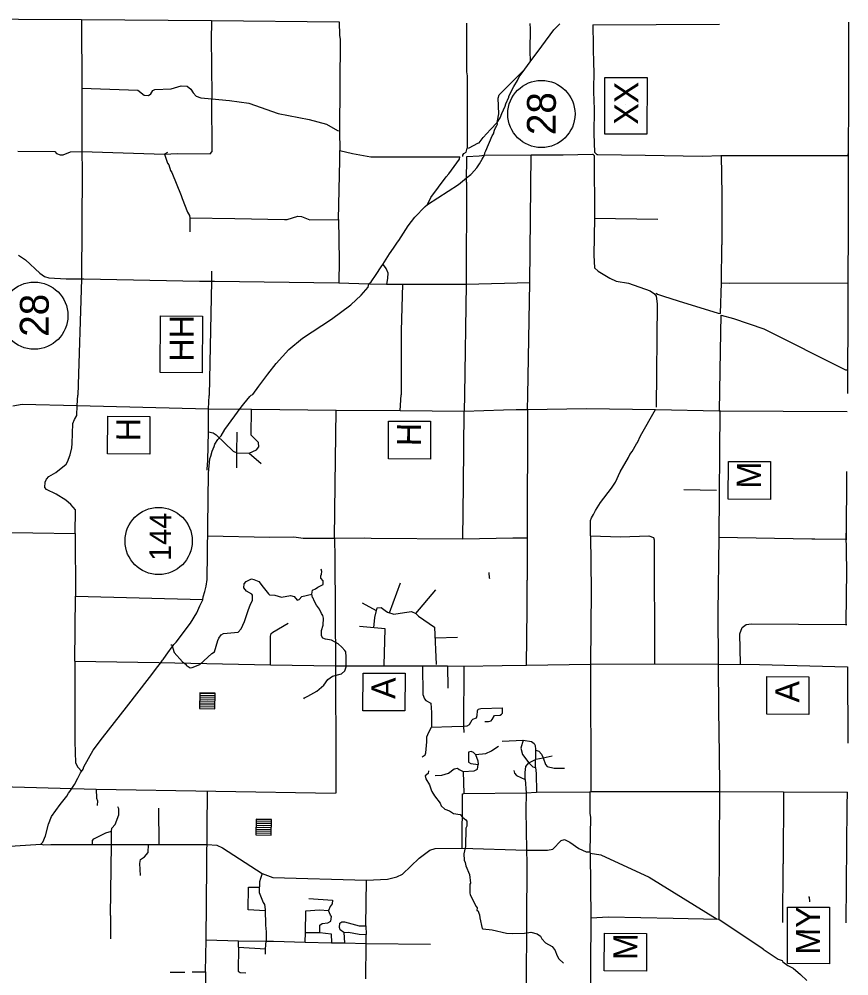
# Model space of a CAD drawing. Extents: x 299354 to 1325680, y 96128 to 228242.
# Drawn here: x 365592 to 400121, y 187967 to 227772 of the extents above; entities that cross this region are included whole.
import ezdxf

# ---------------------------------------------------------------- set-up
doc = ezdxf.new("R2010")
doc.units = 0
for name, color, linetype in [('Level 12', 7, 'Continuous'), ('Level 13', 7, 'Continuous'), ('Level 2', 7, 'Continuous'), ('Level 4', 7, 'Continuous'), ('Level 51', 7, 'Continuous'), ('Level 57', 7, 'Continuous')]:
    doc.layers.add(name, color=color, linetype=linetype)

msp = doc.modelspace()

# ---------------------------------------------------------------- linework, layer by layer
at = {"layer": 'Level 12'}
for p, q in [((387326, 223827), (387326, 223827)), ((366223, 215436), (366223, 215436)), ((371396, 206061), (371396, 206061))]:
    msp.add_line(p, q, dxfattribs=at)
for centre in [(387326, 223827), (366223, 215436), (371396, 206061)]:
    msp.add_circle(centre, 1398, dxfattribs=at)
at = {"layer": 'Level 13'}
for p, q in [((390818, 224213), (390818, 224213)), ((372319, 214294), (372319, 214294)), ((370132, 210496), (370132, 210496)), ((381816, 210290), (381816, 210290)), ((395959, 208614), (395959, 208614)), ((380754, 199812), (380754, 199812)), ((397557, 199665), (397557, 199665)), ((398418, 189701), (398418, 189701)), ((390800, 188986), (390800, 188986))]:
    msp.add_line(p, q, dxfattribs=at)
for points in [[(391711, 222982), (389961, 222989), (389970, 225344), (391720, 225337)], [(373211, 213063), (371461, 213070), (371471, 215425), (373221, 215418)], [(371026, 209675), (369276, 209682), (369282, 211252), (371032, 211245)], [(382710, 209469), (380960, 209476), (380966, 211046), (382716, 211039)], [(396853, 207792), (395103, 207800), (395109, 209370), (396859, 209362)], [(381648, 198990), (379898, 198997), (379904, 200567), (381654, 200560)], [(398451, 198844), (396701, 198851), (396708, 200421), (398458, 200414)], [(399311, 188470), (397561, 188477), (397570, 190832), (399320, 190825)], [(391694, 188164), (389944, 188171), (389950, 189741), (391700, 189734)]]:
    msp.add_lwpolyline(points, close=True, dxfattribs=at)
at = {"layer": 'Level 2'}
for points in [[(384951, 222118), (384968, 222210), (385019, 222293), (385275, 222916), (385326, 222999), (385377, 223148), (385412, 223248), (385437, 223289), (385505, 223406), (385489, 223472), (385607, 223671), (385676, 223846), (385812, 224145), (385846, 224253), (385974, 224519), (385974, 224569), (386178, 224975), (386330, 225224), (386398, 225365), (386635, 225688), (386854, 225995), (387344, 226641), (387842, 227320), (388053, 227535), (388086, 227574)], [(389471, 227539), (389488, 225813), (389504, 225688)], [(385489, 223472), (385559, 223830), (385531, 224489), (385566, 224622), (386113, 225159), (386635, 225688)], [(389504, 225688), (389496, 224746), (389522, 224029), (389513, 222995), (389540, 222236), (389630, 222135), (389676, 222134)], [(385202, 223175), (385489, 223472)], [(384730, 222620), (384908, 222852), (385202, 223175)], [(384236, 222408), (384320, 222415), (384680, 222612), (384730, 222620)], [(380140, 216766), (380241, 216840), (380444, 217147), (380655, 217470), (380723, 217570), (381010, 218009), (381171, 218241), (381340, 218498), (381391, 218564), (381788, 219170), (382058, 219534), (382488, 219972), (382589, 220063), (383872, 220894), (384208, 221166), (384385, 221306), (384418, 221331), (384637, 221579), (384756, 221753), (384866, 221952), (384951, 222118)], [(384050, 222059), (384050, 222118), (384101, 222184), (384201, 222233)], [(384201, 222233), (384236, 222408)], [(384951, 222118), (386894, 222126), (387120, 222124), (387286, 222122), (388237, 222131), (389455, 222153), (389464, 222147)], [(389464, 222147), (389522, 222103), (389532, 219493), (389509, 217951), (389538, 217425), (389687, 217282), (390176, 216994), (390442, 216875), (390951, 216792), (391850, 216461), (392033, 216342), (392107, 216249), (392138, 215930), (392103, 211623)], [(382589, 220063), (382725, 220345), (383366, 221207), (383468, 221339), (383915, 221944), (383933, 222044)], [(365562, 217954), (365852, 217752), (366456, 217204), (366647, 217069), (366830, 217009), (367555, 216969), (368206, 216964), (368289, 216963), (373101, 216870), (373601, 216866), (373726, 216865), (378897, 216794), (380140, 216766)], [(373596, 216867), (373596, 216864), (373496, 212108)], [(375247, 212122), (375314, 212155), (375561, 212498), (375944, 213006), (376284, 213448), (376817, 214023), (377384, 214498), (378584, 215296), (379398, 215881), (379827, 216286), (380114, 216625), (380140, 216766)], [(365003, 193346), (366497, 193449), (366581, 193532), (366692, 193789), (366813, 194272), (366933, 194595), (367296, 195101), (367582, 195440), (367650, 195572), (367701, 195639), (367896, 195928), (368031, 196194), (368150, 196418), (368252, 196567), (368278, 196667), (368668, 197355), (369064, 197876), (370060, 199142), (371022, 200384), (371360, 200839), (371470, 200971), (371554, 201095), (371588, 201129), (371707, 201311), (372036, 201749), (372120, 201849), (372720, 202643), (372990, 203074), (373118, 203365), (373237, 203614), (373255, 203738), (373324, 203955), (373342, 204071), (373376, 204179), (373412, 204462), (373469, 208887), (373525, 209478), (373576, 209594), (373620, 209794), (373705, 209985), (373739, 210084), (373858, 210283), (373994, 210442), (374156, 210693), (374830, 211629), (374949, 211763), (375188, 212072), (375247, 212122)], [(373477, 211562), (373496, 212108)], [(365331, 211685), (365715, 211749), (368008, 211695)], [(368008, 211695), (373477, 211562)], [(373469, 210595), (373477, 211562)], [(373477, 211562), (375262, 211546)], [(375262, 211546), (378781, 211497)], [(378781, 211497), (381450, 211490)], [(381450, 211490), (384110, 211465)], [(384110, 211465), (385753, 211517), (386279, 211529), (386754, 211525)], [(386754, 211525), (389207, 211569), (392075, 211527)], [(392075, 211527), (394718, 211470), (400055, 211452)], [(394746, 211496), (394703, 206219)], [(373421, 209004), (373421, 209054), (373441, 209412), (373469, 210595)], [(394703, 206219), (394674, 203086), (394688, 200936)], [(371409, 200998), (376056, 200913)], [(376056, 200913), (378758, 200872)], [(378758, 200872), (382378, 200873)], [(382378, 200873), (383412, 200863)], [(383412, 200863), (384095, 200857)], [(384095, 200857), (385689, 200876)], [(385689, 200876), (386706, 200892)], [(386706, 200892), (389367, 200934)], [(389367, 200934), (392028, 200943)], [(392028, 200943), (394688, 200936)], [(394688, 200936), (394686, 200694), (394709, 197852), (394722, 197427), (394739, 195635)], [(394688, 200936), (396397, 200921)], [(396397, 200921), (400058, 200821)], [(394739, 195635), (394710, 190918)], [(394710, 190918), (394707, 190327)], [(389386, 190375), (389347, 184284)], [(389386, 190375), (390112, 190419), (392814, 190361), (394701, 190327)], [(394707, 190327), (396553, 189087)], [(396559, 189083), (397185, 188663), (397351, 188612)], [(397351, 188612), (397367, 188545), (397574, 188393), (397807, 188291)], [(397807, 188291), (398113, 188030)], [(398113, 188030), (398378, 187777)]]:
    msp.add_lwpolyline(points, dxfattribs=at)
at = {"layer": 'Level 4'}
for points in [[(368194, 227744), (362929, 227772)], [(368194, 227744), (368202, 224893)], [(373600, 227703), (368194, 227744)], [(373591, 227716), (373583, 226863)], [(378904, 227649), (373600, 227703)], [(378903, 227658), (378904, 227649), (378924, 227107), (378955, 226924), (378921, 223122)], [(384204, 227602), (384215, 225585), (384230, 225409), (384236, 222408)], [(386848, 227589), (386858, 227362), (386850, 226462), (386854, 225995)], [(389471, 227539), (394742, 227566)], [(400110, 227645), (400110, 226211), (400090, 220333)], [(373583, 226863), (373591, 225920)], [(400110, 226211), (400121, 226211)], [(373591, 225920), (373611, 224453)], [(368202, 224893), (370529, 224822), (370794, 224603), (370969, 224601), (371069, 224667), (371154, 224800), (371238, 224841), (371922, 224868), (372340, 224998), (372582, 224979), (372731, 224861), (372830, 224702), (372954, 224567), (373153, 224499), (373611, 224453)], [(368202, 224893), (368200, 223684)], [(371773, 222226), (371639, 222153), (372165, 222181), (373541, 222169), (373625, 222260), (373611, 224453)], [(373611, 224453), (374353, 224388), (375153, 224272), (376367, 223845), (377657, 223592), (378381, 223402), (378838, 223139), (378921, 223122)], [(368200, 223684), (368203, 222258)], [(378921, 223122), (378939, 222313)], [(365543, 222273), (367077, 222260), (367152, 222176), (367301, 222124), (367418, 222123), (367728, 222254), (368203, 222258)], [(368203, 222258), (368211, 221456), (368194, 216951), (368033, 212127)], [(368203, 222258), (371639, 222153), (371769, 221785), (371818, 221709), (371891, 221475), (371941, 221391), (372332, 220437), (372373, 220303), (372601, 219743), (372684, 219600), (372699, 219508)], [(378931, 221900), (378939, 222313)], [(378939, 222313), (379471, 222175), (380221, 222043), (383849, 222044), (383933, 222044)], [(384742, 222078), (384951, 222118)], [(386847, 216815), (386894, 222126)], [(389676, 222134), (391646, 222106)], [(394802, 222098), (400080, 222104), (400107, 222192)], [(394806, 222109), (394837, 220455), (394835, 218387)], [(378888, 219429), (378931, 221900)], [(384207, 220991), (384225, 222058)], [(384225, 222058), (384742, 222078)], [(391646, 222106), (394017, 222071), (394802, 222098)], [(384207, 220991), (384193, 216747)], [(400090, 220330), (400088, 219881)], [(400088, 219863), (400061, 212193)], [(372699, 219508), (372693, 218921)], [(372699, 219508), (374568, 219484), (376636, 219432), (376744, 219431)], [(376744, 219431), (377196, 219577), (377346, 219559), (377687, 219423), (378888, 219429)], [(378888, 219429), (378906, 217736), (378897, 216794)], [(389532, 219493), (392167, 219453)], [(394820, 216795), (394835, 218387)], [(380723, 217570), (380871, 217377), (380936, 217210), (380918, 216976), (380882, 216751)], [(373591, 217291), (373596, 216901)], [(380140, 216766), (380882, 216751)], [(380882, 216751), (381541, 216746)], [(381541, 216746), (381494, 214800), (381486, 212142)], [(381541, 216746), (384193, 216747)], [(384193, 216747), (384130, 212135)], [(384193, 216747), (386847, 216815)], [(386759, 212118), (386847, 216815)], [(394776, 215528), (394820, 216795)], [(394820, 216795), (395137, 216792), (400092, 216807), (400096, 216807)], [(392106, 216369), (392155, 216335), (392405, 216241), (393012, 216052), (394684, 215545), (394776, 215528)], [(394783, 213978), (394808, 215461)], [(394808, 215461), (395316, 215323), (396580, 214887), (399976, 213181), (400043, 213180)], [(394740, 211460), (394783, 213978)], [(368008, 211695), (368033, 212127)], [(381450, 211490), (381486, 212142)], [(384130, 212135), (384110, 211465)], [(386754, 211525), (386759, 212118)], [(367925, 206378), (367934, 207362), (367745, 207580), (367529, 207765), (367140, 208011), (366733, 208198), (366667, 208282), (366669, 208507), (366737, 208639), (366830, 208738), (367115, 208911), (367543, 209257), (367611, 209356), (367714, 209647), (367783, 209938), (367801, 210121), (367826, 210955), (367902, 211120), (367987, 211286), (368008, 211695)], [(375170, 209713), (375463, 209852), (375565, 209984), (375549, 210151), (375252, 210462), (375262, 211546)], [(378743, 208415), (378781, 211497)], [(384082, 208398), (384110, 211465)], [(386754, 211525), (386738, 206192)], [(389366, 206268), (389372, 206909), (389407, 207026), (389491, 207167), (389576, 207333), (389788, 207656), (390244, 208260), (390404, 208508), (390608, 208932), (390956, 209537), (391007, 209653), (391108, 209777), (391278, 210109), (391329, 210158), (391456, 210432), (392075, 211527)], [(373469, 210595), (373660, 210560), (373793, 210475), (374495, 209802), (374653, 209734)], [(374653, 209734), (374661, 210584)], [(374647, 209109), (374653, 209734)], [(374653, 209734), (375170, 209713)], [(375170, 209713), (375658, 209284)], [(400016, 208946), (400007, 206138)], [(400016, 208946), (400022, 208950)], [(378715, 206172), (378743, 208415)], [(384061, 206149), (384082, 208398)], [(394618, 208162), (393253, 208191)], [(362618, 205135), (363636, 205142), (363844, 205190), (363896, 205315), (363918, 205890), (364019, 206072), (364281, 206395), (364381, 206427), (367925, 206378)], [(367925, 206378), (367935, 203770)], [(373429, 206279), (376022, 206222)], [(376022, 206222), (377023, 206229), (377414, 206184)], [(384061, 206149), (386130, 206197), (386738, 206192)], [(386738, 206192), (386739, 204425)], [(389366, 206268), (390617, 206240), (391802, 206279), (391993, 206211), (392025, 206110), (392028, 200943)], [(389366, 206268), (389395, 204017), (389367, 200934)], [(394703, 206219), (398581, 206151), (398706, 206150), (400007, 206138)], [(400015, 202553), (400011, 202673), (400031, 204823), (400012, 206381)], [(377414, 206184), (378715, 206172)], [(378715, 206172), (379958, 206186), (380242, 206184), (384061, 206149)], [(378715, 206172), (378724, 205347)], [(400007, 206138), (400036, 206138)], [(378724, 205347), (378758, 200872)], [(381004, 203069), (381457, 204314)], [(386728, 203208), (386739, 204425)], [(382099, 203049), (382930, 204026)], [(367910, 201062), (367935, 203770)], [(367935, 203770), (373237, 203622)], [(380460, 203160), (379875, 203468)], [(380346, 202452), (380388, 202877), (380495, 203280), (380659, 203298), (380821, 203175), (380918, 203096), (381179, 203013), (381453, 203051), (381728, 203100), (381925, 203128), (382099, 203049), (382206, 202937), (382884, 202474)], [(386706, 200892), (386728, 203208)], [(376056, 200913), (376051, 202105), (376085, 202205), (376152, 202271), (376789, 202640)], [(395606, 200944), (395587, 202199), (395680, 202460), (395841, 202591), (396074, 202607), (399983, 202579)], [(380783, 200888), (380827, 202408), (379756, 202497)], [(382884, 202474), (382949, 200919)], [(382899, 202025), (383828, 202059)], [(367910, 201062), (367912, 197720), (367937, 196836), (368036, 196652), (368201, 196467)], [(367910, 201062), (371409, 200998)], [(378758, 200872), (378770, 196755)], [(382378, 200873), (382392, 199672), (382457, 199488), (382523, 199421), (382722, 199311), (382752, 198927), (382746, 198319)], [(383412, 200863), (383428, 199938)], [(384095, 200857), (384089, 198357)], [(389367, 200934), (389385, 195642)], [(400058, 200821), (400078, 197646)], [(384089, 198357), (384239, 198372), (384340, 198421), (384442, 198620), (384467, 198654), (384618, 198702), (384652, 198802), (384670, 198993), (384688, 199060), (384805, 199092), (385706, 199117)], [(384975, 198549), (385125, 198548), (385242, 198580), (385276, 198630), (385377, 198795), (385603, 198818), (385670, 198851), (385704, 198901), (385706, 199117)], [(382359, 197081), (382485, 197163), (382519, 197246), (382557, 197704), (382559, 197912), (382644, 198112), (382746, 198319)], [(382746, 198319), (383597, 198345), (384089, 198357)], [(384089, 198357), (384103, 198098)], [(384587, 197177), (385013, 197224), (385247, 197330), (385432, 197461), (385541, 197527)], [(385693, 197726), (386561, 197768)], [(386561, 197768), (386466, 197435), (386538, 197176), (386802, 196824)], [(386561, 197768), (386910, 197715), (387026, 197630), (387067, 197547), (387082, 197380), (387099, 197363)], [(384587, 197177), (384504, 197261), (384396, 197304), (384296, 197272), (384292, 196863), (384392, 196796), (384700, 196760)], [(384587, 197177), (384685, 196910), (384700, 196760)], [(387095, 196988), (387099, 197363)], [(387095, 196988), (387396, 197035)], [(387099, 197363), (387215, 197312), (387331, 197186), (387396, 197035)], [(387396, 197035), (387772, 197115)], [(387396, 197035), (387494, 196768), (387568, 196675), (387851, 196606), (388293, 196602)], [(378770, 196755), (378776, 195572)], [(384072, 196474), (384531, 196503), (384665, 196568), (384700, 196760)], [(386646, 196142), (386648, 196434), (386684, 196683), (386802, 196824)], [(386802, 196824), (387079, 196972)], [(386802, 196824), (386967, 196664), (387075, 196630)], [(387075, 196630), (387079, 196972)], [(387079, 196972), (387095, 196988)], [(382902, 196301), (383186, 196315), (383462, 196396), (383697, 196577), (383831, 196609), (383897, 196559), (384072, 196474)], [(384072, 196474), (384097, 195557)], [(386174, 196505), (386206, 196404), (386289, 196304), (386646, 196142)], [(387075, 196630), (387107, 196380), (387116, 195613)], [(362587, 195468), (362737, 195483), (363265, 195762), (363466, 195827), (364300, 195853), (368794, 195729)], [(386646, 196142), (386691, 195583)], [(368794, 195729), (368808, 195362), (368857, 195253), (368838, 195053)], [(368794, 195729), (378764, 195570)], [(373374, 189470), (373431, 195655)], [(384025, 193274), (384046, 195541)], [(384046, 195541), (384097, 195557)], [(384097, 195557), (386691, 195583)], [(386691, 195583), (386684, 194858), (386702, 193200)], [(386691, 195583), (387116, 195613)], [(387116, 195613), (389335, 195626)], [(389335, 195626), (389385, 195642)], [(389335, 195626), (389343, 194734), (389375, 194559), (389345, 193126)], [(389385, 195642), (394739, 195635)], [(394739, 195635), (397399, 195628)], [(397399, 195628), (397383, 192626)], [(397399, 195628), (400060, 195604)], [(400009, 190172), (400054, 195004), (400054, 195046), (400060, 195604)], [(369437, 193981), (369455, 194114), (369590, 194271), (369744, 194670), (369746, 194912), (369697, 194995)], [(371398, 194947), (371400, 193438)], [(368648, 193430), (368650, 193597), (368700, 193663), (369195, 193917), (369437, 193981)], [(369432, 193439), (369437, 193981)], [(386702, 193200), (387586, 193192), (387803, 193240), (388148, 193595), (388282, 193644), (388515, 193533), (388888, 193263), (389195, 193127), (389345, 193126)], [(366513, 193449), (366613, 193415)], [(366613, 193415), (366905, 193429)], [(366905, 193429), (368648, 193430)], [(368648, 193430), (369432, 193439)], [(369388, 190473), (369432, 193439)], [(369432, 193439), (370975, 193426)], [(370638, 192137), (370609, 192645), (370644, 192803), (370812, 192919), (370955, 193101), (370975, 193426)], [(370975, 193426), (371400, 193438)], [(371400, 193438), (373410, 193437)], [(373410, 193437), (373819, 193400), (374059, 193298), (375709, 192233)], [(380043, 191952), (380928, 191994), (381304, 192082), (381539, 192197), (382237, 192865), (382682, 193203), (382908, 193267), (384025, 193274)], [(384025, 193274), (386702, 193200)], [(386702, 193200), (386714, 192675), (386678, 185150)], [(389345, 193126), (389361, 193076)], [(389361, 193076), (389386, 190375)], [(389361, 193076), (389802, 192997), (391811, 192079)], [(397366, 190194), (397383, 192626)], [(375709, 192233), (375641, 192025), (375589, 191875), (375585, 191434), (375748, 191024), (375797, 190940), (375829, 190723), (375840, 190081), (375870, 189806), (375867, 189414)], [(375709, 192233), (376150, 192054), (380043, 191952)], [(380026, 190043), (380043, 191952)], [(391811, 192079), (394640, 190328)], [(375830, 190678), (375119, 190712), (375133, 191655), (375587, 191658)], [(377651, 191182), (378626, 191123), (378625, 190965), (378540, 190849), (378472, 190683)], [(397376, 191320), (397382, 191319)], [(398441, 191261), (398468, 191260), (398483, 191043)], [(377513, 189775), (377521, 190675), (378097, 190719), (378472, 190683)], [(378105, 189769), (378108, 190078), (378200, 190143), (378434, 190175), (378568, 190240), (378587, 190440), (378554, 190490), (378472, 190683)], [(369388, 190473), (369393, 189513)], [(379106, 189777), (378957, 189878), (378924, 189978), (378943, 190153), (379027, 190219), (379127, 190218), (379742, 190046), (380026, 190043)], [(380026, 190043), (380039, 189685)], [(373345, 188137), (373374, 189470)], [(373374, 189470), (374716, 189425)], [(377493, 189366), (377513, 189775)], [(377513, 189775), (378105, 189769)], [(378105, 189769), (378580, 189715), (378593, 189340)], [(379106, 189777), (379298, 189792), (379739, 189704), (380039, 189685)], [(379106, 189777), (379135, 189335)], [(380036, 189310), (380039, 189685)], [(374714, 189158), (374704, 188158), (374787, 188108), (375029, 188089)], [(374714, 189158), (374716, 189425)], [(374714, 189158), (375847, 189098)], [(374716, 189425), (375867, 189414)], [(375845, 188873), (375847, 189098)], [(375847, 189098), (375867, 189414)], [(375867, 189414), (376175, 189412), (377493, 189366)], [(377493, 189366), (378593, 189340)], [(378593, 189340), (379135, 189335)], [(379135, 189335), (380036, 189310)], [(380022, 187843), (380036, 189310)], [(380036, 189310), (382713, 189286)], [(371874, 188120), (372487, 188127)], [(372797, 188131), (373345, 188137)], [(373345, 188137), (373338, 186051)]]:
    msp.add_lwpolyline(points, dxfattribs=at)
at = {"layer": 'Level 51'}
for p, q in [((373104, 199492), (373749, 199478)), ((373105, 199492), (373750, 199478)), ((373106, 199572), (373751, 199558)), ((373107, 199572), (373752, 199558)), ((373108, 199652), (373753, 199638)), ((373108, 199652), (373753, 199638)), ((373109, 199732), (373754, 199718)), ((373110, 199732), (373755, 199718)), ((373097, 199172), (373742, 199158)), ((373098, 199172), (373743, 199158)), ((373099, 199252), (373744, 199238)), ((373100, 199252), (373745, 199238)), ((373101, 199332), (373746, 199318)), ((373102, 199412), (373747, 199398)), ((373102, 199332), (373747, 199318)), ((373103, 199412), (373748, 199398)), ((373416, 199419), (373416, 199419)), ((373417, 199419), (373417, 199419)), ((375447, 194316), (376092, 194302)), ((375448, 194316), (376093, 194302)), ((375449, 194396), (376094, 194382)), ((375450, 194396), (376095, 194382)), ((375451, 194476), (376096, 194462)), ((375452, 194476), (376097, 194462)), ((375439, 193916), (376084, 193902)), ((375440, 193916), (376085, 193902)), ((375441, 193996), (376086, 193982)), ((375441, 193996), (376085, 193982)), ((375442, 194076), (376087, 194062)), ((375443, 194076), (376088, 194062)), ((375444, 194156), (376089, 194142)), ((375445, 194156), (376090, 194142)), ((375446, 194236), (376091, 194222)), ((375447, 194236), (376091, 194222)), ((375757, 194163), (375757, 194163)), ((375758, 194163), (375758, 194163))]:
    msp.add_line(p, q, dxfattribs=at)
for points in [[(373111, 199749), (373096, 199092), (373741, 199078), (373756, 199735)], [(373110, 199749), (373096, 199092), (373740, 199078), (373755, 199735)], [(375451, 194493), (375437, 193836), (376082, 193822), (376096, 194479)], [(375452, 194493), (375438, 193836), (376083, 193822), (376097, 194479)]]:
    msp.add_lwpolyline(points, close=True, dxfattribs=at)
at = {"layer": 'Level 57'}
for points in [[(377769, 203848), (377804, 204014), (377921, 204063), (378022, 204137), (378072, 204170), (378240, 204252), (378241, 204402), (378142, 204519), (378143, 204611), (378177, 204677), (378195, 204794), (378156, 204894)], [(385181, 204489), (385164, 204522), (385150, 204731), (385158, 204753)], [(371945, 201734), (372050, 201424), (372397, 201038), (372538, 200928), (372538, 200895), (372703, 200777), (372787, 200793), (373113, 200923), (373282, 201080), (373610, 201377), (373727, 201443), (373865, 201916), (373899, 202016), (374000, 202157), (374093, 202206), (374702, 202267), (374837, 202399), (374973, 202706), (375136, 203213), (375204, 203396), (375306, 203595), (375308, 203803), (375275, 203854), (375051, 203972), (374936, 204107), (374954, 204281), (375038, 204381), (375264, 204479), (375364, 204461), (375564, 204376), (375753, 204141), (375968, 203864), (376017, 203814), (376226, 203812), (376508, 203726), (376884, 203789), (377034, 203754), (377166, 203603), (377241, 203619), (377359, 203751), (377769, 203848)], [(377437, 199500), (377471, 199534), (377605, 199599), (377982, 199812), (378276, 200068), (378445, 200300), (378630, 200440), (379006, 200536), (379141, 200652), (379200, 200818), (379202, 200951), (379196, 201243), (379181, 201443), (379148, 201502), (379016, 201636), (378867, 201788), (378594, 201940), (378344, 201976), (378236, 202018), (378170, 202119), (378172, 202336), (378241, 202560), (378252, 202843), (378228, 202960), (378179, 203044), (378097, 203220), (377965, 203388), (377866, 203572), (377834, 203680), (377801, 203714), (377769, 203848)], [(371911, 201734), (371945, 201734)], [(382622, 196504), (382612, 196387), (382495, 196288), (382510, 196163), (382675, 195911), (382739, 195702), (382764, 195636), (382879, 195451), (383110, 195157), (383159, 195040), (383307, 194906), (383499, 194837), (383664, 194719), (383939, 194683), (384038, 194574), (384187, 194456), (384220, 194406), (384218, 194189), (384184, 194114), (384161, 193356), (384125, 193173), (384091, 193048), (384105, 192782), (384154, 192681), (384186, 192539), (384333, 192188), (384380, 191829), (384346, 191779), (384343, 191421), (384359, 191338), (384613, 190860), (384646, 190793), (384645, 190693)], [(384645, 190693), (384678, 190693), (384743, 190509), (384759, 190384), (384855, 189941), (384888, 189925), (385279, 189888), (385870, 189749), (386112, 189730), (386621, 189742), (386888, 189790), (387146, 189721), (387295, 189619), (387344, 189502), (387501, 189342), (387767, 189190), (387899, 189022), (387963, 188830), (388054, 188679), (388252, 188494)]]:
    msp.add_lwpolyline(points, dxfattribs=at)

# ---------------------------------------------------------------- texts
at = {"layer": 'Level 12'}
for s, height, p in [('28', 1200, (387922, 222946)), ('28', 1200, (366819, 214555)), ('144', 900, (371913, 205230))]:
    msp.add_text(s, height=height, rotation=89.767, dxfattribs=at).set_placement(p)
at = {"layer": 'Level 13'}
for s, p in [('XX', (391351, 223379)), ('HH', (372852, 213523)), ('H', (370631, 210211)), ('H', (382315, 210005)), ('M', (396457, 208242)), ('A', (381252, 199487)), ('A', (398056, 199340)), ('MY', (398915, 188848)), ('M', (391321, 188624))]:
    msp.add_text(s, height=1000, rotation=89.767, dxfattribs=at).set_placement(p)

doc.saveas('drawing.dxf')
